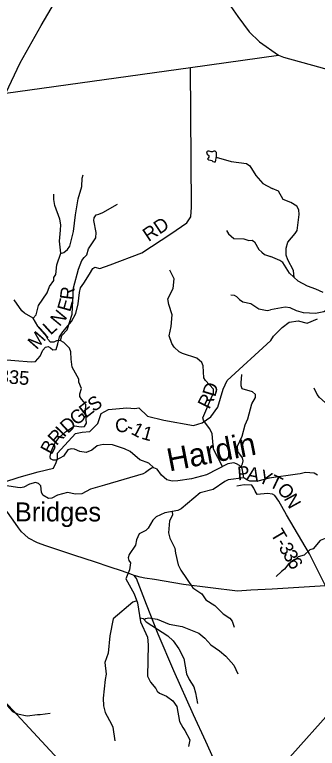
# Model space of a CAD drawing. Extents: x 1525783 to 1900577, y 218250 to 627376.
# Drawn here: x 1679963 to 1686599, y 471228 to 487300 of the extents above; entities that cross this region are included whole.
import ezdxf

# ---------------------------------------------------------------- set-up
doc = ezdxf.new("R2010")
doc.units = 0
for name, color, linetype in [('GM_X_County_Road', 7, 'Continuous'), ('GM_X_County_Road_Text', 7, 'Continuous'), ('GM_X_Minor_Lake', 7, 'Continuous'), ('GM_X_Minor_River', 7, 'Continuous'), ('GM_X_Minor_River_Text', 7, 'Continuous'), ('GM_X_State_Route', 7, 'Continuous'), ('GM_X_Township', 7, 'Continuous'), ('GM_X_Township_Road', 7, 'Continuous'), ('GM_X_Township_Road_Text', 7, 'Continuous'), ('GM_X_Unincorporated_Text', 7, 'Continuous')]:
    doc.layers.add(name, color=color, linetype=linetype)

msp = doc.modelspace()

# ---------------------------------------------------------------- linework, layer by layer
at = {"layer": 'GM_X_County_Road'}
for points in [[(1678836, 479140), (1678862, 479194), (1678886, 479811), (1678909, 480999), (1678928, 481605), (1678942, 481793), (1678985, 481938), (1679102, 482095), (1679185, 482239), (1679245, 482488), (1679303, 482700), (1679550, 483481), (1679617, 483868), (1679644, 484417), (1679687, 485164), (1679692, 485330), (1679717, 485460), (1679766, 485581), (1680085, 486247), (1680544, 487060), (1681032, 487904)], [(1684549, 487702), (1684858, 487257), (1685107, 486924), (1685329, 486708), (1685749, 486416), (1685856, 486370), (1686624, 486158), (1688081, 485750), (1689329, 485402), (1690371, 485071), (1690977, 484925), (1691361, 484820)], [(1679722, 477056), (1680058, 477170), (1680475, 477286), (1680811, 477369), (1680870, 477487), (1680899, 477576), (1680899, 477694), (1681298, 478123), (1681445, 478152), (1681608, 478167), (1681785, 478344), (1681859, 478566), (1682021, 478654), (1682420, 478684), (1682597, 478669), (1682686, 478684), (1682878, 478506), (1683232, 478418), (1683882, 478300), (1684074, 478359), (1684266, 478492), (1684414, 478699), (1684532, 479097), (1684620, 479289), (1685580, 480161), (1685636, 480258), (1685826, 480446), (1685979, 480567), (1686176, 480592), (1686377, 480544), (1686604, 480637)], [(1687770, 473280), (1687722, 473334), (1687528, 473535), (1687416, 473640), (1687267, 473775), (1687165, 473878), (1687090, 473986), (1687047, 474127), (1687020, 474254), (1686982, 474360), (1686970, 474504), (1686938, 474619), (1686871, 474723), (1686780, 474791), (1685609, 474717), (1685141, 474692), (1684846, 474673), (1683661, 474814), (1683032, 474924), (1682816, 474956), (1682716, 474975), (1682586, 475011)]]:
    msp.add_lwpolyline(points, dxfattribs=at)
at = {"layer": 'GM_X_Minor_Lake'}
for points in [[(1684387, 484194), (1684388, 484222), (1684385, 484277), (1684373, 484297), (1684355, 484309), (1684331, 484310), (1684302, 484292), (1684272, 484292), (1684248, 484299), (1684224, 484307), (1684198, 484310), (1684170, 484296), (1684181, 484244), (1684217, 484213), (1684220, 484177), (1684202, 484157), (1684192, 484139), (1684215, 484119), (1684253, 484112), (1684286, 484108), (1684309, 484085), (1684337, 484073), (1684351, 484073)], [(1684351, 484073), (1684365, 484074), (1684387, 484194)]]:
    msp.add_lwpolyline(points, dxfattribs=at)
at = {"layer": 'GM_X_Minor_River'}
for points in [[(1684384, 484179), (1684707, 484081), (1685048, 484040), (1685117, 483991), (1685253, 483774), (1685407, 483601), (1685610, 483491)], [(1680968, 482065), (1681041, 482087), (1681118, 482154), (1681171, 482226), (1681254, 482547), (1681298, 482912), (1681354, 483262), (1681434, 483534), (1681445, 483720), (1681466, 483788)], [(1686090, 481544), (1686078, 481693), (1685951, 481928), (1685915, 482032), (1685913, 482183), (1685951, 482313), (1686110, 482503), (1686153, 482572), (1686202, 482923), (1686193, 483027), (1686146, 483106), (1686021, 483184), (1685848, 483254), (1685747, 483432), (1685610, 483491)], [(1680370, 480655), (1680435, 480728), (1680486, 480930), (1680679, 481210), (1680730, 481348), (1680818, 481477), (1680823, 481539), (1680864, 481608), (1680890, 481817), (1680972, 482076), (1680944, 482341), (1680968, 482582), (1680972, 482698), (1680953, 482821), (1680843, 483117), (1680821, 483248), (1680821, 483371)], [(1680965, 480163), (1680999, 480274), (1681115, 480397), (1681227, 480740), (1681239, 481029), (1681254, 481318), (1681360, 481725), (1681434, 481913), (1681487, 481982), (1681548, 482041), (1681578, 482169), (1681744, 482409), (1681748, 482528), (1681698, 482793), (1681705, 482849), (1681750, 482913), (1681805, 482932), (1681896, 482969), (1682220, 483152)], [(1684609, 482575), (1684648, 482500), (1684771, 482398), (1684988, 482390), (1685100, 482356), (1685172, 482361), (1685224, 482320), (1685318, 482153), (1685378, 482094), (1685441, 482049), (1685569, 482001)], [(1686726, 481213), (1686565, 481290), (1686384, 481352), (1686179, 481461), (1685991, 481634), (1685840, 481869), (1685777, 481918), (1685569, 482001)], [(1684519, 477402), (1684321, 477784), (1684292, 478119), (1684239, 478230), (1684145, 478348), (1684100, 478419), (1684090, 478471), (1684324, 479018), (1684325, 479094), (1684145, 479287), (1684112, 479348), (1684094, 479609), (1684065, 479682), (1683958, 479777), (1683640, 479875), (1683570, 479912), (1683459, 480018), (1683410, 480093), (1683351, 480264), (1683396, 480466), (1683414, 480725), (1683345, 480948), (1683323, 481073), (1683441, 481298), (1683460, 481512), (1683367, 481700)], [(1683015, 477370), (1682906, 477476), (1682708, 477548), (1682496, 477729), (1682372, 477788), (1682105, 477878), (1681906, 477885), (1681771, 477855), (1681651, 477758), (1681532, 477708), (1681393, 477730), (1681272, 477782), (1681201, 477791), (1681127, 477767), (1681034, 477630), (1680876, 477540), (1680808, 477543), (1680748, 477568), (1680739, 477618), (1680769, 477746), (1680846, 477911), (1680938, 478036), (1681009, 478101), (1681076, 478159), (1681277, 478296), (1681420, 478274), (1681492, 478281), (1681541, 478348), (1681517, 478609), (1681522, 478758), (1681480, 478822), (1681429, 478877), (1681390, 478934), (1681391, 478992), (1681425, 479114), (1681368, 479251), (1681370, 479318), (1681221, 479577), (1681205, 479754), (1681196, 479912), (1681163, 479991), (1681040, 480121), (1680963, 480165), (1680882, 480158), (1680818, 480129), (1680747, 480128), (1680690, 480191), (1680629, 480310), (1680515, 480426), (1680469, 480479), (1680370, 480655), (1680180, 480758), (1680121, 480815), (1679954, 481051)], [(1684704, 481161), (1684774, 481154), (1684828, 481129), (1684892, 481058), (1684963, 481007), (1685141, 480974), (1685317, 480854), (1685501, 480823), (1685573, 480834)], [(1686969, 480925), (1686742, 480790), (1686557, 480752), (1686295, 480770), (1686142, 480814), (1686006, 480880), (1685890, 480894), (1685573, 480834)], [(1684920, 477391), (1684959, 477457), (1684974, 477525), (1684959, 477595), (1684856, 477729), (1684850, 477846), (1684950, 478063), (1685014, 478313), (1685076, 478446), (1685166, 478776), (1685242, 478913), (1685245, 478981), (1685178, 479038), (1684948, 479100), (1684925, 479169), (1684932, 479233), (1684943, 479417)], [(1687408, 477072), (1687305, 477171), (1687180, 477221), (1687042, 477231), (1686984, 477276), (1686939, 477473), (1686952, 477796), (1686971, 478008), (1686893, 478629), (1686876, 478695), (1686839, 478746), (1686647, 478913), (1686594, 478982), (1686526, 479115)], [(1685544, 477149), (1685296, 477079), (1685122, 477083), (1685052, 477108), (1684986, 477156), (1684947, 477359), (1684894, 477422), (1684828, 477463), (1684770, 477480), (1684639, 477464), (1684172, 477222), (1683839, 477135), (1683541, 477091), (1683416, 477079), (1683300, 477109), (1683179, 477209), (1683089, 477345), (1683015, 477370), (1682964, 477365), (1682891, 477318), (1682834, 477267), (1682782, 477238), (1681932, 476992), (1681628, 476906), (1681439, 476805), (1681294, 476795), (1681120, 476834), (1680902, 476775), (1680775, 476711), (1680708, 476700), (1680577, 476776), (1680548, 476843), (1680536, 476977), (1680489, 477032), (1680423, 477049), (1680287, 477015), (1680162, 476953), (1680093, 476938), (1680025, 476945), (1679789, 476979)], [(1684986, 477156), (1684644, 477107), (1684571, 477074), (1684313, 476899), (1684027, 476823), (1683612, 476472), (1683539, 476441), (1683257, 476384), (1683066, 476298), (1682995, 476229), (1682890, 476048), (1682835, 475997), (1682689, 475927), (1682633, 475795), (1682611, 475681), (1682475, 475473), (1682448, 475401), (1682467, 475340), (1682500, 475290), (1682484, 475139), (1682403, 474940), (1682584, 474614), (1682656, 474417), (1682725, 474002), (1682873, 473667), (1682892, 473492), (1682872, 472812), (1682940, 472679), (1683058, 472540), (1683087, 472484), (1683139, 472435), (1683290, 472368), (1683427, 472266), (1683516, 472146), (1683575, 471816), (1683653, 471683), (1683695, 471618), (1683804, 471413), (1683777, 471269)], [(1686601, 477211), (1686531, 477258), (1686341, 477267), (1686223, 477244), (1686166, 477233), (1685544, 477149)], [(1687011, 476754), (1687038, 476597), (1687202, 476405), (1687176, 476279), (1687076, 476148), (1686965, 475935), (1686906, 475867), (1686767, 475823), (1686660, 475779), (1686507, 475602), (1686437, 475575), (1686307, 475457), (1686180, 475420), (1686107, 475353), (1685970, 475279), (1685878, 475154), (1685813, 475099), (1685696, 474992)], [(1683416, 476416), (1683421, 476333), (1683358, 476209), (1683338, 475951), (1683365, 475830), (1683474, 475616), (1683486, 475501), (1683550, 475249), (1683609, 475128), (1683866, 474741), (1684065, 474614), (1684153, 474478), (1684348, 474356), (1684532, 474177), (1684679, 474082), (1684730, 474011), (1684776, 473880)], [(1682640, 474459), (1682553, 474430), (1682122, 474062), (1682048, 473692), (1682014, 473311), (1681942, 473111), (1681966, 472854), (1681950, 472738), (1681904, 472327), (1681911, 472161), (1681947, 472012), (1682086, 471759), (1682113, 471692), (1682158, 471391)], [(1682712, 474084), (1682783, 474069), (1682846, 473996), (1683323, 473696), (1683436, 473584), (1683560, 473405), (1683671, 473195), (1683732, 472859), (1683790, 472734), (1683892, 472576), (1683928, 472447), (1683971, 472213)], [(1682801, 474048), (1682833, 474075), (1682903, 474084), (1683084, 474057), (1683353, 473950), (1683636, 473894), (1684001, 473750), (1684134, 473639), (1684264, 473493), (1684455, 473366), (1684596, 473247), (1684765, 473050), (1684855, 472858)], [(1678388, 473852), (1678406, 473852), (1678606, 473658), (1678665, 473537), (1678734, 473480), (1679063, 473298), (1679100, 473243), (1679111, 473159), (1679129, 472932), (1679183, 472801), (1679304, 472704), (1679500, 472593), (1679565, 472532), (1679637, 472378), (1679680, 472295), (1679913, 472037), (1680028, 471981), (1680239, 471942), (1680462, 471966), (1680522, 471973), (1680744, 472000)]]:
    msp.add_lwpolyline(points, dxfattribs=at)
at = {"layer": 'GM_X_State_Route'}
for points in [[(1679981, 476154), (1679895, 476279), (1679805, 476400), (1679708, 476510), (1679616, 476588), (1679272, 476824), (1679166, 476902), (1679050, 477015), (1679000, 477079), (1678930, 477190), (1678895, 477266), (1678864, 477340), (1678836, 477459), (1678822, 477556), (1678817, 477662), (1678828, 478092), (1678843, 478513)], [(1684386, 470863), (1684151, 471379), (1683887, 471961), (1683450, 472925), (1683107, 473727), (1682854, 474378), (1682632, 474948), (1682615, 474980), (1682586, 475011), (1682543, 475032), (1682324, 475108), (1682035, 475205), (1681736, 475308), (1681258, 475463), (1680648, 475665), (1680461, 475732), (1680268, 475832), (1680175, 475910), (1680115, 475970), (1680050, 476056), (1679981, 476154)]]:
    msp.add_lwpolyline(points, dxfattribs=at)
at = {"layer": 'GM_X_Township'}
for points in [[(1687887, 473152), (1685013, 469942), (1684435, 469296), (1683480, 468230), (1682380, 469414), (1677903, 474234), (1677892, 474245), (1673725, 475671), (1673353, 475922), (1671573, 477128), (1667288, 480031), (1666516, 480555), (1666377, 480649), (1665529, 481223), (1663129, 481658), (1661714, 481914), (1660969, 482050), (1656369, 482883), (1656342, 482882), (1650243, 482694)], [(1667288, 480031), (1671573, 477128), (1673353, 475922), (1673725, 475671), (1677892, 474245), (1677903, 474234), (1682380, 469414)], [(1681470, 456885), (1681125, 458352), (1681051, 459368), (1681041, 459491), (1680884, 461471), (1680640, 464558), (1680603, 465023), (1683480, 468230), (1684435, 469296), (1685013, 469942), (1687887, 473152)]]:
    msp.add_lwpolyline(points, dxfattribs=at)
at = {"layer": 'GM_X_Township_Road'}
for points in [[(1679768, 485581), (1683817, 486144), (1685749, 486416)], [(1678886, 479811), (1680328, 479696), (1680416, 479703), (1680521, 479821), (1680580, 479951), (1680641, 480019), (1680700, 480034), (1680752, 480002), (1680800, 479955), (1680876, 479967), (1680911, 480091), (1680948, 480243), (1681019, 480349), (1681207, 480575), (1681301, 480751), (1681358, 480969), (1681384, 481216), (1681404, 481316), (1681477, 481418), (1681601, 481612), (1681678, 481741), (1681721, 481769), (1681827, 481741), (1682060, 481821), (1682751, 482080), (1683383, 482499), (1683734, 482743), (1683825, 482871), (1683838, 483082), (1683817, 486144)], [(1686780, 474791), (1686426, 475491), (1685919, 476341), (1685756, 476644), (1685665, 476768), (1685613, 476799), (1685505, 476808), (1685282, 476791), (1685232, 476862), (1685204, 476931), (1685163, 476992), (1684993, 477002), (1684835, 476973)]]:
    msp.add_lwpolyline(points, dxfattribs=at)

# ---------------------------------------------------------------- texts
at = {"layer": 'GM_X_County_Road_Text'}
for s, rotation, p in [('D', 73.3132, (1684358, 478912)), ('S', 34.8511, (1681694, 478586)), ('R', 63.7491, (1684229, 478641)), ('E', 38.0614, (1681521, 478450)), ('G', 38.6763, (1681316, 478286)), ('D', 42.6579, (1681126, 478111)), ('C', 4.0703, (1682176, 478144)), ('I', 46.4518, (1681045, 478025)), ('-', 338.8683, (1682388, 478166)), ('1', 331.8452, (1682494, 478126)), ('R', 47.3023, (1680879, 477845)), ('1', 344.6368, (1682725, 478012)), ('B', 61.4674, (1680772, 477644))]:
    msp.add_text(s, height=300, rotation=rotation, dxfattribs=at).set_placement(p)
at = {"layer": 'GM_X_Minor_River_Text'}
msp.add_text('Hardin', height=500, rotation=11.0281, dxfattribs=at).set_placement((1683353, 477292))
at = {"layer": 'GM_X_Township_Road_Text'}
for s, rotation, p in [('RD', 33.9574, (1682898, 482316)), ('R', 82.9827, (1681248, 481038)), ('E', 74.3011, (1681178, 480774)), ('N', 50.4691, (1680948, 480453)), ('L', 41.9473, (1680748, 480268)), ('M', 48.7077, (1680445, 479947)), ('I', 41.1279, (1680652, 480184)), ('T-335', 355.5158, (1679227, 479266)), ('P', 4.8473, (1684857, 477098)), ('A', 348.4136, (1685036, 477117)), ('Y', 336.8842, (1685280, 477069)), ('T', 334.6463, (1685520, 476966)), ('O', 310.1232, (1685696, 476891)), ('N', 298.8692, (1685857, 476702)), ('T', 300.5933, (1685564, 475926)), ('-', 300.5795, (1685679, 475732)), ('3', 300.5407, (1685741, 475626)), ('3', 300.3917, (1685835, 475467)), ('6', 299.7062, (1685928, 475309))]:
    msp.add_text(s, height=300, rotation=rotation, dxfattribs=at).set_placement(p)
at = {"layer": 'GM_X_Unincorporated_Text'}
msp.add_text('Bridges', height=417, rotation=0, dxfattribs=at).set_placement((1679967, 476199))

doc.saveas('drawing.dxf')
